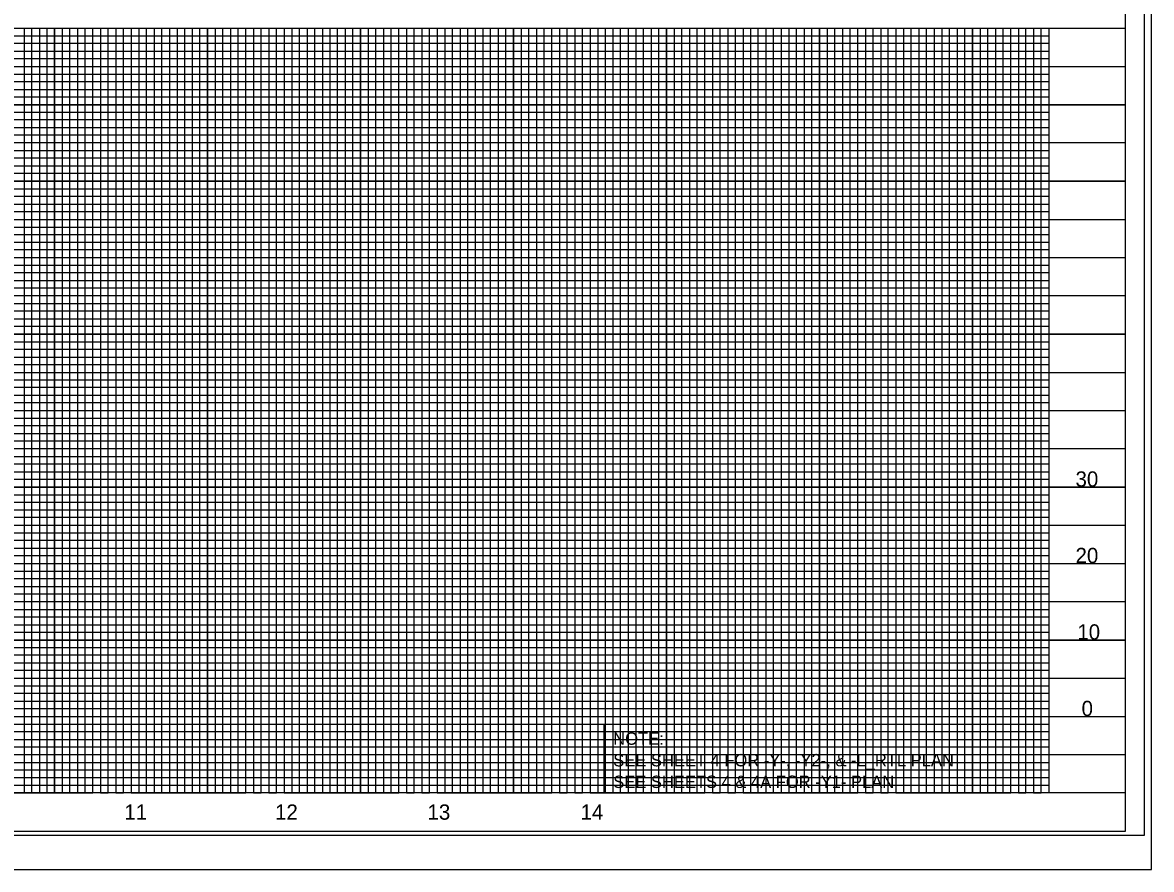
# Model space of a CAD drawing. Extents: x 2180324 to 2182216, y 74532 to 75632.
# Drawn here: x 2181270 to 2182008, y 74532 to 75086 of the extents above; entities that cross this region are included whole.
import ezdxf

# ---------------------------------------------------------------- set-up
doc = ezdxf.new("R2010")
doc.units = 0
for name, color, linetype in [('Exist Structure Minor Culvert Topo', 7, 'Continuous'), ('Exist Structure Minor Culvert Topo Terminator', 7, 'Continuous'), ('Exist Structure Minor Footbridge Terminator', 7, 'Continuous'), ('Old_Level_1', 7, 'Continuous'), ('Old_Level_11', 7, 'Continuous'), ('Old_Level_2', 7, 'Continuous'), ('Old_Level_3', 7, 'Continuous'), ('Scratch_Level_0', 7, 'Continuous'), ('Sheet Border Standard 30in CELL', 7, 'Continuous'), ('Sheet Cutting Line CELL', 7, 'Continuous'), ('Sheet Plot Border Outside CELL', 7, 'Continuous'), ('Sheet Sticker Exception Certification CELL', 7, 'Continuous'), ('Sheet Sticker Incomplete CELL', 7, 'Continuous'), ('Sheet Sticker Preliminary CELL', 7, 'Continuous')]:
    doc.layers.add(name, color=color, linetype=linetype)

msp = doc.modelspace()

# ---------------------------------------------------------------- linework, layer by layer
at = {"layer": 'Exist Structure Minor Culvert Topo'}
msp.add_lwpolyline([(2181240.9, 75082.28), (2181940.9, 75082.28), (2181940.9, 74582.28), (2181240.9, 74582.28)], close=True, dxfattribs=at)
at = {"layer": 'Exist Structure Minor Culvert Topo Terminator'}
msp.add_lwpolyline([(2181650.23, 74627.28), (2181940.9, 74627.28), (2181940.9, 74582.28), (2181650.23, 74582.28)], close=True, dxfattribs=at)
at = {"layer": 'Old_Level_11'}
for p, q in [((2180490.9, 75082.28), (2181990.79, 75082.28)), ((2181290.9, 75082.28), (2181290.9, 74582.28)), ((2181340.9, 75082.28), (2181340.9, 74582.28)), ((2181390.9, 75082.28), (2181390.9, 74582.28)), ((2181440.9, 75082.28), (2181440.9, 74582.28)), ((2181490.9, 75082.28), (2181490.9, 74582.28)), ((2181540.9, 75082.28), (2181540.9, 74582.28)), ((2181590.9, 75082.28), (2181590.9, 74582.28)), ((2181640.9, 75082.28), (2181640.9, 74582.28)), ((2181690.9, 75082.28), (2181690.9, 74582.28)), ((2181740.9, 75082.28), (2181740.9, 74582.28)), ((2181790.9, 75082.28), (2181790.9, 74582.28)), ((2181840.9, 75082.28), (2181840.9, 74582.28)), ((2181890.9, 75082.28), (2181890.9, 74582.28)), ((2181940.9, 75082.28), (2181940.9, 74582.28)), ((2180490.9, 75032.28), (2181990.79, 75032.28)), ((2180490.9, 74982.28), (2181990.79, 74982.28)), ((2180490.9, 74932.28), (2181990.79, 74932.28)), ((2180490.9, 74882.28), (2181990.79, 74882.28)), ((2180490.9, 74832.28), (2181990.79, 74832.28)), ((2180490.9, 74782.28), (2181990.79, 74782.28)), ((2180490.9, 74732.28), (2181990.79, 74732.28)), ((2180490.9, 74682.28), (2181990.79, 74682.28)), ((2180490.9, 74632.28), (2181990.79, 74632.28))]:
    msp.add_line(p, q, dxfattribs=at)
at = {"layer": 'Old_Level_2'}
for points in [[(2181265.9, 74582.28), (2181315.9, 74582.28), (2181315.9, 75082.28), (2181365.9, 75082.28), (2181365.9, 74582.28), (2181415.9, 74582.28), (2181415.9, 75082.28), (2181465.9, 75082.28), (2181465.9, 74582.28), (2181515.9, 74582.28), (2181515.9, 75082.28), (2181565.9, 75082.28), (2181565.9, 74582.28), (2181615.9, 74582.28), (2181615.9, 75082.28), (2181665.9, 75082.28), (2181665.9, 74582.28), (2181715.9, 74582.28), (2181715.9, 75082.28), (2181765.9, 75082.28), (2181765.9, 74582.28), (2181815.9, 74582.28), (2181815.9, 75082.28), (2181865.9, 75082.28), (2181865.9, 74582.28), (2181915.9, 74582.28), (2181915.9, 75082.28)], [(2180490.9, 75057.28), (2181990.9, 75057.28)], [(2181990.9, 75007.28), (2180490.9, 75007.28), (2180490.9, 74957.28), (2181990.9, 74957.28)], [(2181990.9, 74907.28), (2180490.9, 74907.28), (2180490.9, 74857.28), (2181990.9, 74857.28)], [(2181990.9, 74807.28), (2180490.9, 74807.28), (2180490.9, 74757.28), (2181990.9, 74757.28)], [(2181990.9, 74707.28), (2180490.9, 74707.28), (2180490.9, 74657.28), (2181990.9, 74657.28)], [(2181990.9, 74607.28), (2180490.9, 74607.28)]]:
    msp.add_lwpolyline(points, dxfattribs=at)
at = {"layer": 'Scratch_Level_0'}
msp.add_line((2180323.9, 74532.28), (2182007.9, 74532.28), dxfattribs=at)
at = {"layer": 'Sheet Border Standard 30in CELL'}
msp.add_lwpolyline([(2180540.9, 75082.28), (2181940.9, 75082.28), (2181940.9, 74582.28), (2180540.9, 74582.28)], close=True, dxfattribs=at)
at = {"layer": 'Sheet Cutting Line CELL'}
for p, q in [((2180490.9, 75082.28), (2181990.9, 75082.28)), ((2181990.9, 74582.28), (2180490.9, 74582.28)), ((2180490.9, 74557.28), (2181990.9, 74557.28))]:
    msp.add_line(p, q, dxfattribs=at)
msp.add_lwpolyline([(2181990.9, 75607.28), (2180490.9, 75607.28), (2180490.9, 74557.28), (2181990.9, 74557.28)], close=True, dxfattribs=at)
at = {"layer": 'Sheet Plot Border Outside CELL'}
for p, q in [((2180540.9, 75077.28), (2181940.9, 75077.28)), ((2181940.9, 75072.28), (2180540.9, 75072.28)), ((2180540.9, 75067.28), (2181940.9, 75067.28)), ((2181940.9, 75062.28), (2180540.9, 75062.28)), ((2180540.9, 75052.28), (2181940.9, 75052.28)), ((2181940.9, 75047.28), (2180540.9, 75047.28)), ((2180540.9, 75042.28), (2181940.9, 75042.28)), ((2181940.9, 75037.28), (2180540.9, 75037.28)), ((2180540.9, 75027.28), (2181940.9, 75027.28)), ((2181940.9, 75022.28), (2180540.9, 75022.28)), ((2180540.9, 75017.28), (2181940.9, 75017.28)), ((2181940.9, 75012.28), (2180540.9, 75012.28)), ((2180540.9, 75002.28), (2181940.9, 75002.28)), ((2181940.9, 74997.28), (2180540.9, 74997.28)), ((2180540.9, 74992.28), (2181940.9, 74992.28)), ((2181940.9, 74987.28), (2180540.9, 74987.28)), ((2180540.9, 74977.28), (2181940.9, 74977.28)), ((2181940.9, 74972.28), (2180540.9, 74972.28)), ((2180540.9, 74967.28), (2181940.9, 74967.28)), ((2181940.9, 74962.28), (2180540.9, 74962.28)), ((2180540.9, 74952.28), (2181940.9, 74952.28)), ((2181940.9, 74947.28), (2180540.9, 74947.28)), ((2180540.9, 74942.28), (2181940.9, 74942.28)), ((2181940.9, 74937.28), (2180540.9, 74937.28)), ((2180540.9, 74927.28), (2181940.9, 74927.28)), ((2181940.9, 74922.28), (2180540.9, 74922.28)), ((2180540.9, 74917.28), (2181940.9, 74917.28)), ((2181940.9, 74912.28), (2180540.9, 74912.28)), ((2180540.9, 74902.28), (2181940.9, 74902.28)), ((2181940.9, 74897.28), (2180540.9, 74897.28)), ((2180540.9, 74892.28), (2181940.9, 74892.28)), ((2181940.9, 74887.28), (2180540.9, 74887.43)), ((2180540.9, 74877.28), (2181940.9, 74877.28)), ((2181940.9, 74872.28), (2180540.9, 74872.28)), ((2180540.9, 74867.28), (2181940.9, 74867.28)), ((2181940.9, 74862.28), (2180540.9, 74862.28)), ((2180540.9, 74852.28), (2181940.9, 74852.28)), ((2181940.9, 74847.28), (2180540.9, 74847.28)), ((2180540.9, 74842.28), (2181940.9, 74842.28)), ((2181940.9, 74837.28), (2180540.9, 74837.28)), ((2180540.9, 74827.28), (2181940.9, 74827.28)), ((2181940.9, 74822.28), (2180540.9, 74822.28)), ((2180540.9, 74817.28), (2181940.9, 74817.28)), ((2181940.9, 74812.28), (2180540.9, 74812.28)), ((2180540.9, 74802.28), (2181940.9, 74802.28)), ((2181940.9, 74797.28), (2180540.9, 74797.28)), ((2180540.9, 74792.28), (2181940.9, 74792.28)), ((2181940.9, 74787.28), (2180540.9, 74787.28)), ((2180540.9, 74777.28), (2181940.9, 74777.28)), ((2181940.9, 74772.28), (2180540.9, 74772.28)), ((2180540.9, 74767.28), (2181940.9, 74767.28)), ((2181940.9, 74762.28), (2180540.9, 74762.28)), ((2180540.9, 74752.28), (2181940.9, 74752.28)), ((2181940.9, 74747.28), (2180540.9, 74747.28)), ((2180540.9, 74742.28), (2181940.9, 74742.28)), ((2181940.9, 74737.28), (2180540.9, 74737.28)), ((2180540.9, 74727.28), (2181940.9, 74727.28)), ((2181940.9, 74722.28), (2180540.9, 74722.28)), ((2180540.9, 74717.28), (2181940.9, 74717.28)), ((2181940.9, 74712.28), (2180540.9, 74712.28)), ((2180540.9, 74702.28), (2181940.9, 74702.28)), ((2181940.9, 74697.28), (2180540.9, 74697.28)), ((2180540.9, 74692.28), (2181940.9, 74692.28)), ((2181940.9, 74687.28), (2180540.9, 74687.28)), ((2180540.9, 74677.28), (2181940.9, 74677.28)), ((2181940.9, 74672.28), (2180540.9, 74672.28)), ((2180540.9, 74667.28), (2181940.9, 74667.28)), ((2181940.9, 74662.28), (2180540.9, 74662.28)), ((2180540.9, 74652.28), (2181940.9, 74652.28)), ((2181940.9, 74647.28), (2180540.9, 74647.28)), ((2180540.9, 74642.28), (2181940.9, 74642.28)), ((2181940.9, 74637.28), (2180540.9, 74637.28)), ((2180540.9, 74627.28), (2181940.9, 74627.28)), ((2181940.9, 74622.28), (2180540.9, 74622.28)), ((2180540.9, 74617.28), (2181940.9, 74617.28)), ((2181940.9, 74612.28), (2180540.9, 74612.28)), ((2180540.9, 74602.28), (2181940.9, 74602.28)), ((2181940.9, 74597.28), (2180540.9, 74597.28)), ((2180540.9, 74592.28), (2181940.9, 74592.28)), ((2180540.9, 74587.28), (2181940.9, 74587.28)), ((2181940.9, 74587.28), (2181940.9, 74587.28)), ((2181940.9, 74587.28), (2181940.9, 74587.28))]:
    msp.add_line(p, q, dxfattribs=at)
for points in [[(2181260.9, 75082.28), (2181270.9, 75082.28), (2181270.9, 74582.28), (2181275.9, 74582.28), (2181275.9, 75082.28), (2181280.9, 75082.28), (2181280.9, 74582.28), (2181285.9, 74582.28), (2181285.9, 75082.28), (2181295.9, 75082.28), (2181295.9, 74582.28), (2181300.9, 74582.28), (2181300.9, 75082.28), (2181305.9, 75082.28), (2181305.9, 74582.28), (2181310.9, 74582.28), (2181310.9, 75082.28), (2181320.9, 75082.28), (2181320.9, 74582.28), (2181325.9, 74582.28), (2181325.9, 75082.28), (2181330.9, 75082.28), (2181330.9, 74582.28), (2181335.9, 74582.28), (2181335.9, 75082.28), (2181345.9, 75082.28), (2181345.9, 74582.28), (2181350.6, 74582.83), (2181350.9, 74582.28), (2181350.9, 75082.28), (2181355.9, 75082.28), (2181355.9, 74582.28), (2181360.9, 74582.28), (2181360.9, 75082.28), (2181370.9, 75082.28), (2181370.9, 74582.28), (2181375.9, 74582.28)], [(2181375.9, 74582.28), (2181375.9, 75082.28), (2181380.9, 75082.28), (2181380.9, 74582.28), (2181385.9, 74582.28), (2181385.9, 75082.28), (2181395.9, 75082.28), (2181395.9, 74582.28), (2181400.9, 74582.28), (2181400.9, 75082.28), (2181405.9, 75082.28), (2181405.9, 74582.28), (2181410.9, 74582.28), (2181410.9, 75082.28), (2181420.9, 75082.28), (2181420.9, 74582.28), (2181425.9, 74582.28), (2181425.9, 75082.28), (2181430.9, 75082.28), (2181430.9, 74582.28), (2181435.9, 74582.28), (2181435.9, 75082.28), (2181445.9, 75082.28), (2181445.9, 74582.28), (2181450.9, 74582.28), (2181450.9, 75082.28), (2181455.9, 75082.28), (2181455.9, 74582.28), (2181460.9, 74582.28), (2181460.9, 75082.28), (2181470.9, 75082.28), (2181470.9, 74582.28), (2181475.9, 74582.28), (2181475.9, 75082.28), (2181480.9, 75082.28), (2181480.9, 74582.28), (2181485.9, 74582.28), (2181485.9, 75082.28), (2181495.9, 75082.28), (2181495.9, 74582.28), (2181500.9, 74582.28), (2181500.9, 75082.28), (2181505.9, 75082.28), (2181505.9, 74582.28), (2181510.9, 74582.28), (2181510.9, 75082.28), (2181520.9, 75082.28), (2181520.9, 74582.28), (2181525.9, 74582.28), (2181525.9, 75082.28), (2181530.9, 75082.28), (2181530.9, 74582.28), (2181535.9, 74582.28), (2181535.9, 75082.28), (2181545.9, 75082.28), (2181545.9, 74582.28), (2181550.9, 74582.28), (2181550.9, 75082.28), (2181555.9, 75082.28), (2181555.9, 74582.28), (2181560.9, 74582.28), (2181560.9, 75082.28), (2181570.9, 75082.28), (2181570.9, 74582.28), (2181575.9, 74582.28), (2181575.9, 75082.28), (2181580.9, 75082.28), (2181580.9, 74582.28), (2181585.9, 74582.28), (2181585.9, 75082.28), (2181595.9, 75082.28), (2181595.9, 74582.28), (2181600.9, 74582.28), (2181600.9, 75082.28), (2181605.9, 75082.28), (2181605.9, 74582.28), (2181610.9, 74582.28), (2181610.9, 75082.28), (2181620.9, 75082.28), (2181620.9, 74582.28), (2181625.9, 74582.28), (2181625.9, 75082.28), (2181630.9, 75082.28), (2181630.9, 74582.28), (2181635.9, 74582.28), (2181635.9, 75082.28), (2181645.9, 75082.28), (2181645.9, 74582.28), (2181650.9, 74582.28), (2181650.9, 75082.28), (2181655.9, 75082.28), (2181655.9, 74582.28), (2181660.9, 74582.28), (2181660.9, 75082.28), (2181670.9, 75082.28), (2181670.9, 74582.28), (2181675.9, 74582.28), (2181675.9, 75082.28), (2181680.9, 75082.28), (2181680.9, 74582.28)], [(2181680.9, 74582.28), (2181685.9, 74582.28), (2181685.9, 75082.28), (2181695.9, 75082.28), (2181695.9, 74582.28), (2181700.9, 74582.28), (2181700.9, 75082.28), (2181705.9, 75082.28), (2181705.9, 74582.28), (2181710.9, 74582.28), (2181710.9, 75082.28), (2181720.9, 75082.28), (2181720.9, 74582.28), (2181725.9, 74582.28), (2181725.9, 75082.28), (2181730.9, 75082.28), (2181730.9, 74582.28), (2181735.9, 74582.28), (2181735.9, 75082.28), (2181745.9, 75082.28), (2181745.9, 74582.28), (2181750.9, 74582.28), (2181750.9, 75082.28), (2181755.9, 75082.28), (2181755.9, 74582.28), (2181760.9, 74582.28), (2181760.9, 75082.28), (2181770.9, 75082.28), (2181770.9, 74582.28), (2181775.9, 74582.28), (2181775.9, 75082.28), (2181780.9, 75082.28), (2181780.9, 74582.28), (2181785.9, 74582.28), (2181785.9, 75082.28), (2181795.9, 75082.28), (2181795.9, 74582.28), (2181800.9, 74582.28), (2181800.9, 75082.28), (2181805.9, 75082.28), (2181805.9, 74582.28), (2181810.9, 74582.28), (2181810.9, 75082.28), (2181820.9, 75082.28), (2181820.9, 74582.28), (2181825.9, 74582.28), (2181825.9, 75082.28), (2181830.9, 75082.28), (2181830.9, 74582.28), (2181835.9, 74582.28), (2181835.9, 75082.28), (2181845.9, 75082.28), (2181845.9, 74582.28), (2181850.9, 74582.28), (2181850.9, 75082.28), (2181855.9, 75082.28), (2181855.9, 74582.28), (2181860.9, 74582.28), (2181860.9, 75082.28), (2181870.9, 75082.28), (2181870.9, 74582.28), (2181875.9, 74582.28), (2181875.9, 75082.28), (2181880.9, 75082.28), (2181880.9, 74582.28), (2181885.9, 74582.28), (2181885.9, 75082.28), (2181895.9, 75082.28), (2181895.9, 74582.28), (2181900.9, 74582.28), (2181900.9, 75082.28), (2181905.9, 75082.28), (2181905.9, 74582.28), (2181910.9, 74582.28), (2181910.9, 75082.28), (2181920.9, 75082.28), (2181920.9, 74582.28), (2181925.9, 74582.28), (2181925.9, 75082.28), (2181930.9, 75082.28), (2181930.9, 74582.28), (2181935.9, 74582.28), (2181935.9, 75082.28), (2181940.9, 75082.28)]]:
    msp.add_lwpolyline(points, dxfattribs=at)
at = {"layer": 'Sheet Sticker Exception Certification CELL'}
for p, q in [((2181290.9, 75082.28), (2181340.9, 75082.28)), ((2181390.9, 75082.28), (2181440.9, 75082.28)), ((2181490.9, 75082.28), (2181540.9, 75082.28)), ((2181590.9, 75082.28), (2181640.9, 75082.28)), ((2181690.9, 75082.28), (2181740.9, 75082.28)), ((2181790.9, 75082.28), (2181840.9, 75082.28)), ((2181890.9, 75082.28), (2181940.9, 75082.28)), ((2181890.9, 74582.28), (2181890.9, 74582.28)), ((2181890.9, 74582.28), (2181890.9, 74582.28))]:
    msp.add_line(p, q, dxfattribs=at)
for points in [[(2181240.9, 74582.28), (2181290.9, 74582.28), (2181290.9, 75082.28), (2181340.9, 75082.28), (2181340.9, 74582.28), (2181390.9, 74582.28), (2181390.9, 75082.28), (2181440.9, 75082.28), (2181440.9, 74582.28), (2181490.9, 74582.28), (2181490.9, 75082.28), (2181540.9, 75082.28), (2181540.9, 74582.28), (2181590.9, 74582.28), (2181590.9, 75082.28), (2181640.9, 75082.28), (2181640.9, 74582.28), (2181690.9, 74582.28), (2181690.9, 75082.28), (2181740.9, 75082.28), (2181740.9, 74582.28), (2181790.9, 74582.28), (2181790.9, 75082.28), (2181840.9, 75082.28), (2181840.9, 74582.28), (2181890.9, 74582.28), (2181890.9, 74582.28), (2181890.9, 75082.28), (2181940.9, 75082.28), (2181940.9, 74582.28)], [(2181990.9, 75032.28), (2180490.9, 75032.28)], [(2181990.9, 74982.28), (2180490.9, 74982.28), (2180490.9, 74932.28), (2181990.9, 74932.28)], [(2181990.9, 74882.28), (2180490.9, 74882.28), (2180490.9, 74832.28), (2181990.9, 74832.28)], [(2181990.9, 74782.28), (2180490.9, 74782.28), (2180490.9, 74732.28), (2181990.9, 74732.28)], [(2181990.9, 74682.28), (2180490.9, 74682.28), (2180490.9, 74682.28), (2180490.9, 74632.28), (2181990.9, 74632.28)], [(2181990.9, 74582.28), (2180490.9, 74582.28)]]:
    msp.add_lwpolyline(points, dxfattribs=at)
at = {"layer": 'Sheet Sticker Incomplete CELL'}
msp.add_lwpolyline([(2180323.9, 74532.28), (2182007.9, 74532.28), (2182007.9, 75632.28), (2180323.9, 75632.28)], close=True, dxfattribs=at)
at = {"layer": 'Sheet Sticker Preliminary CELL'}
msp.add_lwpolyline([(2180336.9, 74554.73), (2182003.4, 74554.73), (2182003.4, 75609.83), (2180336.9, 75609.83)], close=True, dxfattribs=at)

# ---------------------------------------------------------------- texts
at = {"layer": 'Exist Structure Minor Footbridge Terminator'}
for s, height, p in [('NOTE:', 8.077, (2181656.07, 74613.78)), ('SEE SHEET 4 FOR -Y-, -Y2-, & -L_RTL PLAN', 8.0769, (2181656.08, 74599.64)), ('SEE SHEETS 4 & 4A FOR -Y1- PLAN', 8.0769, (2181656.08, 74585.51))]:
    msp.add_text(s, height=height, rotation=0.02303, dxfattribs=at).set_placement(p)
at = {"layer": 'Old_Level_1'}
for s, p in [('11', (2181336.44, 74564.78)), ('12', (2181434.99, 74564.78)), ('13', (2181534.66, 74564.78)), ('14', (2181634.72, 74564.78))]:
    msp.add_text(s, height=10, dxfattribs=at).set_placement(p)
at = {"layer": 'Old_Level_3'}
for s, p in [('30', (2181958.29, 74782.53)), ('30', (2181958.29, 74782.53)), ('20', (2181958.29, 74732.53)), ('20', (2181958.29, 74732.53)), ('10', (2181959.49, 74682.53)), ('10', (2181959.49, 74682.53)), ('0', (2181962.24, 74632.53)), ('0', (2181962.24, 74632.53))]:
    msp.add_text(s, height=10, dxfattribs=at).set_placement(p)

doc.saveas('drawing.dxf')
